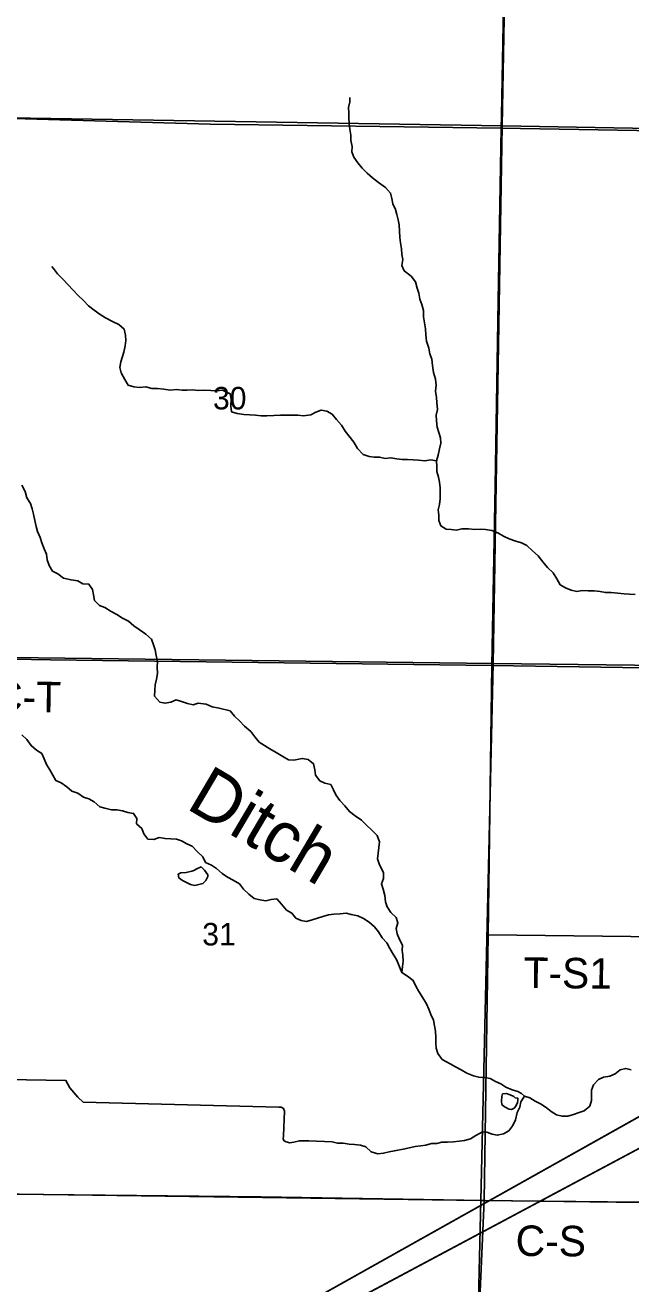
# Model space of a CAD drawing. Extents: x -6.2 to 37.4, y 0.2 to 22.2.
# Drawn here: x 3.005 to 3.568, y 18.286 to 19.457 of the extents above; entities that cross this region are included whole.
import ezdxf

# ---------------------------------------------------------------- set-up
doc = ezdxf.new("R2010")
doc.units = 0
for name, color, linetype in [('GM_X_County_Road', 7, 'Continuous'), ('GM_X_County_Road_Text', 7, 'Continuous'), ('GM_X_Minor_Lake', 7, 'Continuous'), ('GM_X_Minor_River', 7, 'Continuous'), ('GM_X_Minor_River_Text', 7, 'Continuous'), ('GM_X_Section', 7, 'Continuous'), ('GM_X_Section_Text', 7, 'Continuous'), ('GM_X_Township_Road', 7, 'Continuous'), ('GM_X_Township_Road_Text', 7, 'Continuous'), ('SH_Border', 7, 'Continuous'), ('SH_Data', 7, 'Continuous')]:
    doc.layers.add(name, color=color, linetype=linetype)

msp = doc.modelspace()

# ---------------------------------------------------------------- linework, layer by layer
at = {"layer": 'GM_X_County_Road'}
for points in [[(3.439, 18.8612), (3.442, 19.0285), (3.4448, 19.2006), (3.4477, 19.3613), (3.4479, 19.3727), (3.4523, 19.6118), (3.453, 19.6458), (3.4561, 19.861)], [(2.9414, 18.8702), (2.9483, 18.8674), (2.9569, 18.8677), (3.0283, 18.8665), (3.439, 18.8612)], [(3.4319, 18.3636), (3.4355, 18.6108), (3.439, 18.8612)], [(3.439, 18.8612), (3.6419, 18.8581), (3.9173, 18.8544), (3.9385, 18.8541), (4.161, 18.8513), (4.4458, 18.8505)], [(2.934, 18.3699), (3.2244, 18.3668), (3.4319, 18.3636), (3.4329, 18.3636)], [(3.4252, 18.1174), (3.424, 18.1871), (3.4319, 18.3636)], [(3.4329, 18.3636), (3.6277, 18.3611), (3.7361, 18.3598), (3.9338, 18.3574), (4.2101, 18.3545), (4.4362, 18.3519), (4.4372, 18.3519)]]:
    msp.add_lwpolyline(points, dxfattribs=at)
at = {"layer": 'GM_X_Minor_Lake'}
for p, q in [((3.16, 18.6698), (3.1547, 18.6687)), ((3.4524, 18.45), (3.4535, 18.4492))]:
    msp.add_line(p, q, dxfattribs=at)
for points in [[(3.1547, 18.6687), (3.1497, 18.6683), (3.1471, 18.667), (3.1479, 18.6637), (3.1513, 18.6612), (3.1586, 18.6576), (3.1626, 18.6566), (3.1703, 18.6584), (3.1729, 18.6613), (3.1748, 18.6649), (3.1749, 18.6666), (3.1717, 18.6708), (3.1686, 18.6738), (3.1646, 18.6721), (3.1619, 18.6705), (3.16, 18.6698)], [(3.4535, 18.4492), (3.4552, 18.4486), (3.4574, 18.4482), (3.4599, 18.4495), (3.4613, 18.4512), (3.4629, 18.4545), (3.4633, 18.4566), (3.4631, 18.4587), (3.4607, 18.4591), (3.4596, 18.4603), (3.4562, 18.4619), (3.4528, 18.4631), (3.449, 18.4626), (3.4482, 18.4603), (3.4481, 18.4558), (3.4484, 18.4527), (3.4509, 18.4506), (3.4524, 18.45)]]:
    msp.add_lwpolyline(points, dxfattribs=at)
at = {"layer": 'GM_X_Minor_River'}
for points in [[(3.34, 19.3062), (3.3335, 19.3108), (3.3281, 19.3151), (3.3229, 19.3194), (3.3183, 19.3242), (3.3142, 19.3291), (3.3107, 19.3342), (3.3088, 19.3394), (3.309, 19.3443), (3.3078, 19.3497), (3.3079, 19.3548), (3.3069, 19.3605), (3.3063, 19.3656), (3.306, 19.3708), (3.3061, 19.3757), (3.3058, 19.3806), (3.3069, 19.3859), (3.307, 19.3899)], [(3.5725, 18.9273), (3.567, 18.9276), (3.5621, 18.9281), (3.5561, 18.9286), (3.5502, 18.9291), (3.5447, 18.9292), (3.5398, 18.9302), (3.5341, 18.9307), (3.5285, 18.9307), (3.5232, 18.9311), (3.5182, 18.9303), (3.5128, 18.9315), (3.5075, 18.9337), (3.5027, 18.9365), (3.4995, 18.9419), (3.4961, 18.9474), (3.4909, 18.9525), (3.4866, 18.9577), (3.4822, 18.9633), (3.477, 18.9681), (3.4716, 18.973), (3.4666, 18.9755), (3.4615, 18.9769), (3.4553, 18.9793), (3.45, 18.9815), (3.4446, 18.9847), (3.439, 18.9869), (3.4331, 18.9879), (3.4282, 18.9882), (3.4233, 18.988), (3.4172, 18.9886), (3.4112, 18.9886), (3.4062, 18.9873), (3.4013, 18.988), (3.3964, 18.9883), (3.3916, 18.9912), (3.3898, 18.9962), (3.3897, 19.0011), (3.3892, 19.0061), (3.3903, 19.011), (3.391, 19.0163), (3.3909, 19.0214), (3.391, 19.0267), (3.3903, 19.0318), (3.3893, 19.0366), (3.3877, 19.0418), (3.3878, 19.0465), (3.3875, 19.0516), (3.3892, 19.0569), (3.3904, 19.0628), (3.3915, 19.0682), (3.3912, 19.073), (3.3896, 19.0781), (3.3882, 19.0831), (3.3876, 19.089), (3.3871, 19.0943), (3.3885, 19.0996), (3.3877, 19.1059), (3.3874, 19.1106), (3.3866, 19.1165), (3.3871, 19.1222), (3.3867, 19.1277), (3.3849, 19.134), (3.3839, 19.1405), (3.3831, 19.1464), (3.3813, 19.1513), (3.3803, 19.1565), (3.3783, 19.1631), (3.3775, 19.169), (3.3772, 19.1747), (3.3764, 19.1801), (3.3754, 19.1858), (3.3753, 19.1915), (3.3739, 19.1972), (3.3721, 19.2021), (3.3711, 19.2077), (3.3697, 19.2124), (3.3679, 19.2182), (3.3639, 19.2235), (3.3574, 19.2286), (3.3554, 19.2334), (3.3561, 19.2391), (3.3554, 19.2438), (3.3549, 19.249), (3.3539, 19.2547), (3.3533, 19.2596), (3.3528, 19.2714), (3.3519, 19.2761), (3.3507, 19.2809), (3.3493, 19.2857), (3.3469, 19.2908), (3.3461, 19.296), (3.3449, 19.3009), (3.34, 19.3062)], [(3.3875, 19.0516), (3.3822, 19.0527), (3.3766, 19.0518), (3.3707, 19.0525), (3.3658, 19.0526), (3.3607, 19.0529), (3.3556, 19.053), (3.3505, 19.0537), (3.3452, 19.0546), (3.3399, 19.0539), (3.3346, 19.0552), (3.3297, 19.0551), (3.3248, 19.0559), (3.3193, 19.0577), (3.3141, 19.0633), (3.3105, 19.0691), (3.3027, 19.0795), (3.2993, 19.0849), (3.2946, 19.0903), (3.2904, 19.0951), (3.2855, 19.098), (3.2803, 19.0989), (3.2753, 19.0969), (3.2705, 19.0944), (3.2639, 19.0937), (3.2584, 19.0942), (3.2525, 19.0943), (3.2423, 19.0942), (3.2362, 19.0939), (3.2296, 19.0937), (3.2245, 19.0936), (3.2192, 19.0941), (3.2139, 19.0944), (3.2083, 19.095), (3.2022, 19.0959), (3.1968, 19.0975), (3.1961, 19.1027), (3.1966, 19.1091), (3.1956, 19.1141), (3.1883, 19.1176), (3.183, 19.1168), (3.1777, 19.1173), (3.1718, 19.1176), (3.1659, 19.1173), (3.1607, 19.1178), (3.1557, 19.1175), (3.1508, 19.1174), (3.1457, 19.1181), (3.1396, 19.1175), (3.134, 19.1183), (3.1281, 19.1192), (3.1226, 19.1191), (3.117, 19.1206), (3.1113, 19.1201), (3.1058, 19.1206), (3.1006, 19.1222), (3.0976, 19.1274), (3.0942, 19.1335), (3.093, 19.1387), (3.094, 19.144), (3.0965, 19.1528), (3.0979, 19.1587), (3.0984, 19.1636), (3.0981, 19.1687), (3.0969, 19.1743), (3.0921, 19.1787), (3.0861, 19.1815), (3.0797, 19.1847), (3.0747, 19.1878), (3.0689, 19.1921), (3.0637, 19.196), (3.059, 19.2008), (3.0542, 19.2055), (3.0496, 19.2105), (3.0444, 19.2157), (3.0403, 19.2205), (3.0348, 19.2258), (3.0311, 19.2306), (3.0298, 19.2327)], [(3.127, 18.8486), (3.1279, 18.8539), (3.1276, 18.8596), (3.1279, 18.8649), (3.1267, 18.8706), (3.1257, 18.8758), (3.1243, 18.8805), (3.1223, 18.8859), (3.1171, 18.8905), (3.1109, 18.8948), (3.1061, 18.8982), (3.1011, 18.9026), (3.0955, 18.9054), (3.0902, 18.9089), (3.0848, 18.9117), (3.079, 18.9152), (3.0741, 18.917), (3.0693, 18.9218), (3.0683, 18.9272), (3.0676, 18.9321), (3.0641, 18.9369), (3.0586, 18.9374), (3.0538, 18.9402), (3.0476, 18.9409), (3.0404, 18.9427), (3.0352, 18.9466), (3.0303, 18.9492), (3.0272, 18.9542), (3.0254, 18.9597), (3.0246, 18.9648), (3.0224, 18.97), (3.0204, 18.9753), (3.0189, 18.9803), (3.0163, 18.9859), (3.0151, 18.9906), (3.0139, 18.9961), (3.0125, 19.0021), (3.0113, 19.007), (3.0097, 19.0122), (3.0064, 19.0172), (3.005, 19.0231), (3.0017, 19.029)], [(3.4694, 18.4605), (3.4667, 18.463), (3.4631, 18.4648), (3.458, 18.4664), (3.4522, 18.469), (3.4473, 18.4719), (3.4425, 18.4743), (3.4376, 18.4769), (3.4319, 18.4779), (3.4268, 18.4782), (3.4219, 18.4794), (3.4159, 18.482), (3.4105, 18.485), (3.4053, 18.4879), (3.4002, 18.4905), (3.3929, 18.4948), (3.3887, 18.5004), (3.3871, 18.5052), (3.3868, 18.5103), (3.3869, 18.515), (3.3867, 18.5211), (3.3858, 18.5261), (3.3848, 18.5314), (3.3822, 18.5366), (3.3803, 18.5415), (3.3781, 18.5465), (3.3748, 18.5519), (3.3711, 18.558), (3.3684, 18.563), (3.3659, 18.5682), (3.3605, 18.5721), (3.3552, 18.5756), (3.3559, 18.5811), (3.3566, 18.5862), (3.3563, 18.5913), (3.3557, 18.5964), (3.3558, 18.6012), (3.3532, 18.6062), (3.3511, 18.6115), (3.35, 18.6166), (3.3515, 18.6217), (3.3499, 18.6267), (3.3452, 18.6315), (3.3416, 18.6367), (3.3401, 18.6415), (3.3395, 18.6474), (3.3379, 18.6531), (3.3363, 18.6581), (3.3381, 18.6631), (3.3381, 18.6686), (3.3344, 18.6759), (3.3325, 18.6815), (3.3333, 18.6868), (3.334, 18.692), (3.3345, 18.6973), (3.3322, 18.7031), (3.3275, 18.7081), (3.3225, 18.7126), (3.3177, 18.7174), (3.3119, 18.7213), (3.3065, 18.7254), (3.3023, 18.7308), (3.2976, 18.7356), (3.2938, 18.7408), (3.2916, 18.7456), (3.2891, 18.7506), (3.2838, 18.7518), (3.2789, 18.754), (3.275, 18.7592), (3.2742, 18.7643), (3.2732, 18.7699), (3.268, 18.7738), (3.2627, 18.7748), (3.2547, 18.7733), (3.2498, 18.7736), (3.2447, 18.7767), (3.2384, 18.7804), (3.2326, 18.7836), (3.2275, 18.7867), (3.2227, 18.79), (3.2184, 18.7949), (3.2148, 18.8), (3.209, 18.8047), (3.2044, 18.8099), (3.1995, 18.8142), (3.1955, 18.8192), (3.1853, 18.8217), (3.1789, 18.8229), (3.1733, 18.8253), (3.1659, 18.8264), (3.1611, 18.8248), (3.1559, 18.8259), (3.1504, 18.8277), (3.1452, 18.8293), (3.1404, 18.8273), (3.1351, 18.8261), (3.1302, 18.8271), (3.1252, 18.8329), (3.1255, 18.8384), (3.1258, 18.8434), (3.127, 18.8486)], [(3.3552, 18.5756), (3.3504, 18.5878), (3.3473, 18.5928), (3.344, 18.598), (3.3412, 18.6032), (3.337, 18.608), (3.3337, 18.6134), (3.3298, 18.6182), (3.325, 18.6225), (3.3196, 18.6258), (3.3145, 18.6284), (3.3083, 18.6296), (3.3034, 18.6307), (3.2979, 18.6302), (3.292, 18.6299), (3.2871, 18.6293), (3.2818, 18.6277), (3.2768, 18.6263), (3.2718, 18.6245), (3.2667, 18.6232), (3.2616, 18.6241), (3.2567, 18.6261), (3.2531, 18.6309), (3.248, 18.6337), (3.2432, 18.6391), (3.2391, 18.6441), (3.2338, 18.6434), (3.2289, 18.6424), (3.2232, 18.6433), (3.2179, 18.6445), (3.2129, 18.6486), (3.2081, 18.6532), (3.2042, 18.6582), (3.1984, 18.6614), (3.193, 18.6642), (3.188, 18.6679), (3.1829, 18.6723), (3.1781, 18.6755), (3.1727, 18.678), (3.1701, 18.6832), (3.1651, 18.6879), (3.1601, 18.6931), (3.1552, 18.6953), (3.1504, 18.698), (3.1455, 18.6998), (3.1404, 18.6999), (3.1351, 18.7002), (3.1294, 18.7013), (3.1246, 18.6995), (3.119, 18.6998), (3.1151, 18.7048), (3.1133, 18.7096), (3.1085, 18.714), (3.1086, 18.7188), (3.1057, 18.7237), (3.1004, 18.7244), (3.0955, 18.726), (3.09, 18.7271), (3.0851, 18.727), (3.0791, 18.7284), (3.0742, 18.7299), (3.069, 18.7343), (3.0641, 18.7373), (3.059, 18.7389), (3.0538, 18.7426), (3.0484, 18.7444), (3.0435, 18.7485), (3.0383, 18.7522), (3.0334, 18.7542), (3.0305, 18.7592), (3.0278, 18.7642), (3.0248, 18.7693), (3.0225, 18.7743), (3.0203, 18.7793), (3.0155, 18.7824), (3.0104, 18.7867), (3.0064, 18.7923), (3.0016, 18.7969)], [(3.5687, 18.485), (3.5636, 18.4863), (3.5585, 18.485), (3.5537, 18.4812), (3.5487, 18.479), (3.543, 18.4783), (3.5383, 18.4762), (3.5336, 18.4711), (3.5316, 18.4662), (3.5317, 18.4613), (3.5316, 18.4564), (3.5302, 18.4513)], [(3.2904, 18.418), (3.2689, 18.419), (3.26, 18.419), (3.2548, 18.4178), (3.251, 18.4171), (3.2478, 18.4179), (3.2458, 18.4189), (3.2449, 18.4206), (3.2451, 18.4236), (3.246, 18.4466), (3.2451, 18.4491), (3.243, 18.4502), (3.2408, 18.4503), (3.0588, 18.4551), (3.054, 18.4597), (3.0464, 18.4684), (3.0427, 18.4751), (2.933, 18.4769)], [(3.5302, 18.4513), (3.525, 18.447), (3.5202, 18.4452), (3.5149, 18.4436), (3.5097, 18.442), (3.5044, 18.4419), (3.4993, 18.4432), (3.4943, 18.4463), (3.4895, 18.45), (3.4842, 18.4533), (3.4792, 18.4559), (3.4743, 18.459), (3.4694, 18.4605), (3.4661, 18.4552), (3.465, 18.4503), (3.4627, 18.4453), (3.461, 18.4386), (3.4586, 18.4334), (3.4547, 18.4283), (3.4498, 18.4256), (3.4441, 18.4242), (3.4392, 18.4252), (3.4343, 18.4269), (3.4302, 18.4275), (3.424, 18.424), (3.4192, 18.4209), (3.4137, 18.4193), (3.4087, 18.4188), (3.4034, 18.418), (3.3979, 18.4177), (3.3926, 18.4176), (3.3879, 18.4164), (3.3828, 18.4165), (3.3776, 18.4149), (3.3729, 18.4144), (3.3677, 18.4136), (3.3582, 18.4115), (3.3484, 18.4098), (3.3436, 18.4088), (3.3383, 18.4076), (3.333, 18.4069), (3.3268, 18.4087), (3.3218, 18.4134), (3.3167, 18.415), (3.3112, 18.4155), (3.3063, 18.416), (3.3006, 18.4168), (3.2955, 18.4169), (3.2904, 18.418)]]:
    msp.add_lwpolyline(points, dxfattribs=at)
at = {"layer": 'GM_X_Section'}
for points in [[(3.4579, 19.8638), (3.4485, 19.3634), (2.9522, 19.3714), (2.9521, 19.374), (2.9594, 19.874)], [(3.9572, 19.8551), (3.9512, 19.3544), (3.4485, 19.3634), (3.4579, 19.8638)], [(2.9522, 19.3714), (3.4485, 19.3634), (3.4402, 18.8631), (2.9418, 18.8694)], [(3.4485, 19.3634), (3.9512, 19.3544), (3.9401, 18.8573), (3.4402, 18.8631)], [(3.4402, 18.8631), (3.4289, 18.3634), (2.9318, 18.3702), (2.9418, 18.8694)], [(3.9401, 18.8573), (3.9301, 18.3582), (3.4289, 18.3634), (3.4402, 18.8631)], [(2.9318, 18.3702), (3.4289, 18.3634), (3.417, 17.8606), (2.9226, 17.8695), (2.9229, 17.8758)], [(3.4289, 18.3634), (3.9301, 18.3582), (3.9187, 17.8532), (3.417, 17.8606)]]:
    msp.add_lwpolyline(points, close=True, dxfattribs=at)
at = {"layer": 'GM_X_Township_Road'}
msp.add_line((3.4355, 18.6108), (3.9352, 18.6044), dxfattribs=at)
for points in [[(2.9509, 19.3716), (3.1771, 19.365), (3.4477, 19.3613)], [(3.4477, 19.3613), (3.9345, 19.3529), (3.9398, 19.3513), (3.9449, 19.3486)]]:
    msp.add_lwpolyline(points, dxfattribs=at)
at = {"layer": 'SH_Border'}
for p, q in [((2.4803, 17.8272), (9.0866, 21.532)), ((9.0866, 21.3538), (2.4803, 17.8272))]:
    msp.add_line(p, q, dxfattribs=at)
at = {"layer": 'SH_Data'}
msp.add_lwpolyline([(9.0866, 21.3538), (2.4803, 17.8272), (9.0866, 21.532)], close=True, dxfattribs=at)

# ---------------------------------------------------------------- texts
at = {"layer": 'GM_X_County_Road_Text'}
for s, rotation, p in [('C-T', 359.1454, (2.9749, 18.8185)), ('C-S', 359.5595, (3.4611, 18.3119))]:
    msp.add_text(s, height=0.02841, rotation=rotation, dxfattribs=at).set_placement(p)
at = {"layer": 'GM_X_Minor_River_Text'}
msp.add_text('Ditch', height=0.04737, rotation=329.4793, dxfattribs=at).set_placement((3.1534, 18.7289))
at = {"layer": 'GM_X_Section_Text'}
for s, p in [('30', (3.1796, 19.0996)), ('31', (3.1696, 18.6008))]:
    msp.add_text(s, height=0.02093, rotation=0, dxfattribs=at).set_placement(p)
at = {"layer": 'GM_X_Township_Road_Text'}
msp.add_text('T-S1', height=0.02841, rotation=359.3129, dxfattribs=at).set_placement((3.4683, 18.5614))

doc.saveas('drawing.dxf')
